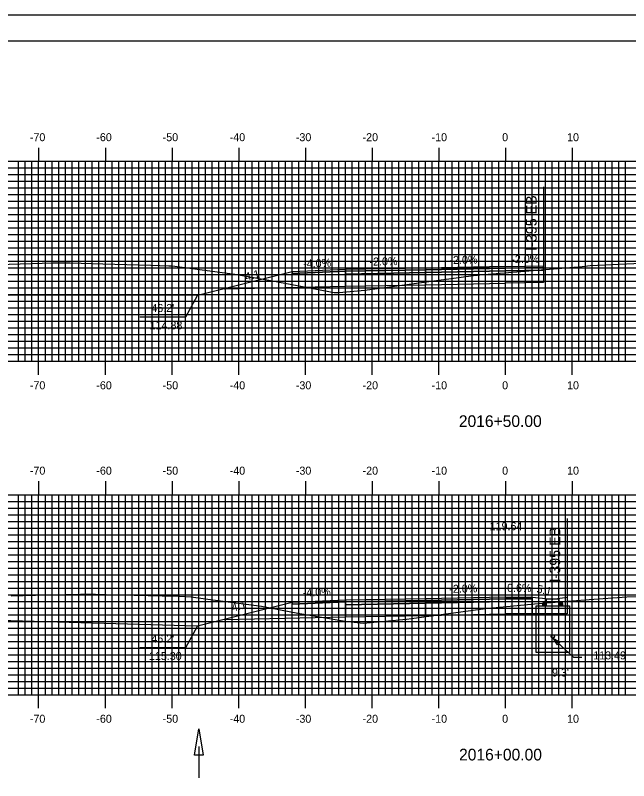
# Model space of a CAD drawing. Extents: x 854681 to 855024, y 366605 to 366825.
# Drawn here: x 854773.1 to 854865.1, y 366710.2 to 366824.9 of the extents above; entities that cross this region are included whole.
import ezdxf

# ---------------------------------------------------------------- set-up
doc = ezdxf.new("R2010")
doc.units = 0
for name, color, linetype in [('ANNOTATION', 7, 'Continuous'), ('BORDER', 7, 'Continuous'), ('D_Drainage_CB_TypeA1-B1', 7, 'Continuous'), ('D_Drainage_Culvert', 7, 'Continuous'), ('D_Drainage_Ditch_Line', 7, 'Continuous'), ('D_Roadway_Centerline', 7, 'Continuous'), ('D_Roadway_Centerline_Text', 7, 'Continuous'), ('D_Roadway_Edge_Shoulder', 7, 'Continuous'), ('D_Roadway_Edge_TW', 7, 'Continuous'), ('D_Roadway_Pavement', 7, 'Continuous'), ('D_Roadway_SlopeLines', 7, 'Continuous'), ('D_Roadway_SubGrade', 7, 'Continuous'), ('D_Text_Standard', 7, 'Continuous'), ('H_V ANNOTATION', 7, 'Continuous'), ('M_Roadway_Centerline', 7, 'Continuous'), ('MAJOR', 7, 'Continuous'), ('MINOR', 7, 'Continuous'), ('PLOT BOUNDARY', 7, 'Continuous'), ('S_Roadway_Centerline', 7, 'Continuous')]:
    doc.layers.add(name, color=color, linetype=linetype)

msp = doc.modelspace()

# ---------------------------------------------------------------- linework, layer by layer
at = {"layer": 'ANNOTATION'}
msp.add_line((854804.38, 366734.36), (854800.38, 366733.36), dxfattribs=at)
for points in [[(854804.38, 366783.93), (854800.38, 366782.93), (854734.03, 366782.96)], [(854791.72, 366779.72), (854798.65, 366779.72), (854800.38, 366782.93)], [(854804.38, 366734.36), (854800.38, 366733.36), (854742.57, 366734.98)], [(854791.72, 366730.15), (854798.65, 366730.15), (854800.38, 366733.36)]]:
    msp.add_lwpolyline(points, dxfattribs=at)
at = {"layer": 'BORDER'}
msp.add_lwpolyline([(854696.96, 366611.06), (855016.96, 366611.06), (855016.96, 366821.06), (854696.96, 366821.06)], close=True, dxfattribs=at)
at = {"layer": 'D_Drainage_CB_TypeA1-B1'}
msp.add_lwpolyline([(854855.17, 366736.78), (854854.64, 366736.78), (854854.64, 366737.41), (854852.67, 366737.41), (854852.67, 366736.78), (854852.15, 366736.78)], dxfattribs=at)
for points in [[(854856.15, 366729.41), (854851.17, 366729.41), (854851.17, 366736.4), (854856.15, 366736.4)], [(854852.67, 366736.72), (854852.67, 366736.47), (854852.17, 366736.47), (854852.17, 366736.72)], [(854855.14, 366736.72), (854855.14, 366736.47), (854854.64, 366736.47), (854854.64, 366736.72)]]:
    msp.add_lwpolyline(points, close=True, dxfattribs=at)
at = {"layer": 'D_Drainage_Culvert'}
msp.add_circle((854853.66, 366731.8), 0.25, dxfattribs=at)
at = {"layer": 'D_Drainage_Ditch_Line'}
msp.add_line((854800.59, 366715.32), (854800.59, 366710.62), dxfattribs=at)
msp.add_lwpolyline([(854801.25, 366714.01), (854799.94, 366714.01), (854800.59, 366717.94)], close=True, dxfattribs=at)
at = {"layer": 'D_Roadway_Centerline'}
for p, q in [((854855.81, 366737.67), (854855.81, 366735.18)), ((854855.81, 366735.18), (854850.56, 366735.18))]:
    msp.add_line(p, q, dxfattribs=at)
msp.add_lwpolyline([(854850.56, 366737.68), (854853.66, 366737.41), (854855.81, 366737.67)], dxfattribs=at)
at = {"layer": 'D_Roadway_Edge_Shoulder'}
for points in [[(854822.56, 366786.8), (854814.56, 366786.48), (854814.56, 366786.23), (854822.56, 366786.55)], [(854846.56, 366787.28), (854852.26, 366787.39), (854852.26, 366787.14), (854846.56, 366787.03)], [(854846.56, 366737.7), (854850.56, 366737.68), (854850.56, 366737.43), (854846.56, 366737.45)], [(854822.56, 366737.22), (854814.56, 366736.9), (854814.56, 366736.65), (854822.56, 366736.97)]]:
    msp.add_lwpolyline(points, close=True, dxfattribs=at)
at = {"layer": 'D_Roadway_Edge_TW'}
for points in [[(854834.56, 366787.04), (854822.56, 366786.8), (854822.56, 366786.55), (854834.56, 366786.79)], [(854846.56, 366787.28), (854834.56, 366787.04), (854834.56, 366786.79), (854846.56, 366787.03)], [(854834.56, 366737.46), (854822.56, 366737.22), (854822.56, 366736.97), (854834.56, 366737.21)], [(854846.56, 366737.7), (854834.56, 366737.46), (854834.56, 366737.21), (854846.56, 366737.45)]]:
    msp.add_lwpolyline(points, close=True, dxfattribs=at)
at = {"layer": 'D_Roadway_Pavement'}
for points in [[(854834.56, 366786.79), (854822.56, 366786.55), (854822.56, 366786.13), (854834.56, 366786.37)], [(854846.56, 366787.03), (854834.56, 366786.79), (854834.56, 366786.37), (854846.56, 366786.61)], [(854846.56, 366787.03), (854852.26, 366787.14), (854852.26, 366786.72), (854846.56, 366786.61)], [(854846.56, 366737.45), (854834.56, 366737.21), (854834.56, 366736.79), (854846.56, 366737.03)], [(854846.56, 366737.45), (854850.56, 366737.43), (854850.56, 366737.01), (854846.56, 366737.03)], [(854834.56, 366737.21), (854822.56, 366736.97), (854822.56, 366736.55), (854834.56, 366736.79)]]:
    msp.add_lwpolyline(points, close=True, dxfattribs=at)
for points in [[(854834.56, 366786.79), (854834.56, 366786.37)], [(854822.56, 366786.55), (854822.56, 366786.13)], [(854822.56, 366786.55), (854822.56, 366786.13)], [(854822.56, 366736.97), (854822.56, 366736.55)], [(854822.56, 366736.97), (854822.56, 366736.55)], [(854834.56, 366737.21), (854834.56, 366736.79)]]:
    msp.add_lwpolyline(points, dxfattribs=at)
at = {"layer": 'D_Roadway_SlopeLines'}
msp.add_line((854814.56, 366736.9), (854800.38, 366733.36), dxfattribs=at)
at = {"layer": 'D_Roadway_SubGrade'}
for p, q in [((854852.26, 366799.2), (854852.26, 366784.89)), ((854855.81, 366749.48), (854855.81, 366735.18))]:
    msp.add_line(p, q, dxfattribs=at)
for points in [[(854846.56, 366786.61), (854852.26, 366786.72), (854852.26, 366787.14), (854852.26, 366787.39), (854852.26, 366784.89), (854846.56, 366784.78)], [(854822.56, 366786.13), (854822.56, 366786.55), (854814.56, 366786.23), (854814.56, 366786.48), (854804.38, 366783.93), (854822.56, 366784.3)], [(854834.56, 366786.37), (854822.56, 366786.13), (854822.56, 366784.3), (854834.56, 366784.54)], [(854846.56, 366786.61), (854834.56, 366786.37), (854834.56, 366784.54), (854846.56, 366784.78)], [(854846.56, 366737.03), (854850.56, 366737.01), (854850.56, 366737.43), (854850.56, 366737.68), (854850.56, 366735.18), (854846.56, 366735.2)], [(854822.56, 366736.55), (854822.56, 366736.97), (854814.56, 366736.65), (854814.56, 366736.9), (854804.38, 366734.36), (854822.56, 366734.72)], [(854834.56, 366736.79), (854822.56, 366736.55), (854822.56, 366734.72), (854834.56, 366734.96)], [(854846.56, 366737.03), (854834.56, 366736.79), (854834.56, 366734.96), (854846.56, 366735.2)]]:
    msp.add_lwpolyline(points, close=True, dxfattribs=at)
at = {"layer": 'D_Text_Standard'}
msp.add_lwpolyline([(854853.66, 366731.55), (854854.31, 366730.54), (854854.71, 366730.96)], close=True, dxfattribs=at)
msp.add_lwpolyline([(854853.66, 366731.55), (854856.76, 366728.67), (854858, 366728.67)], dxfattribs=at)
at = {"layer": 'MAJOR'}
for p, q in [((854776.56, 366805.06), (854776.56, 366803.06)), ((854786.56, 366805.06), (854786.56, 366803.06)), ((854796.56, 366805.06), (854796.56, 366803.06)), ((854806.56, 366805.06), (854806.56, 366803.06)), ((854816.56, 366805.06), (854816.56, 366803.06)), ((854826.56, 366805.06), (854826.56, 366803.06)), ((854836.56, 366805.06), (854836.56, 366803.06)), ((854846.56, 366805.06), (854846.56, 366803.06)), ((854856.56, 366805.06), (854856.56, 366803.06)), ((854706.56, 366803.06), (854986.56, 366803.06)), ((854706.56, 366803.06), (854986.56, 366803.06)), ((854776.56, 366773.06), (854776.56, 366803.06)), ((854786.56, 366773.06), (854786.56, 366803.06)), ((854796.56, 366773.06), (854796.56, 366803.06)), ((854806.56, 366773.06), (854806.56, 366803.06)), ((854816.56, 366773.06), (854816.56, 366803.06)), ((854826.56, 366773.06), (854826.56, 366803.06)), ((854836.56, 366773.06), (854836.56, 366803.06)), ((854846.56, 366773.06), (854846.56, 366803.06)), ((854856.56, 366773.06), (854856.56, 366803.06)), ((854706.56, 366798.06), (854986.56, 366798.06)), ((854706.56, 366793.06), (854986.56, 366793.06)), ((854706.56, 366788.06), (854986.56, 366788.06)), ((854706.56, 366783.06), (854986.56, 366783.06)), ((854706.56, 366778.06), (854986.56, 366778.06)), ((854706.56, 366773.06), (854986.56, 366773.06)), ((854706.56, 366773.06), (854986.56, 366773.06)), ((854776.56, 366771.05), (854776.56, 366773.06)), ((854786.56, 366771.05), (854786.56, 366773.06)), ((854796.56, 366771.05), (854796.56, 366773.06)), ((854806.56, 366771.05), (854806.56, 366773.06)), ((854816.56, 366771.05), (854816.56, 366773.06)), ((854826.56, 366771.05), (854826.56, 366773.06)), ((854836.56, 366771.05), (854836.56, 366773.06)), ((854846.56, 366771.05), (854846.56, 366773.06)), ((854856.56, 366771.05), (854856.56, 366773.06)), ((854776.56, 366755.06), (854776.56, 366753.06)), ((854786.56, 366755.06), (854786.56, 366753.06)), ((854796.56, 366755.06), (854796.56, 366753.06)), ((854806.56, 366755.06), (854806.56, 366753.06)), ((854816.56, 366755.06), (854816.56, 366753.06)), ((854826.56, 366755.06), (854826.56, 366753.06)), ((854836.56, 366755.06), (854836.56, 366753.06)), ((854846.56, 366755.06), (854846.56, 366753.06)), ((854856.56, 366755.06), (854856.56, 366753.06)), ((854706.56, 366753.06), (854986.56, 366753.06)), ((854706.56, 366753.06), (854986.56, 366753.06)), ((854776.56, 366723.06), (854776.56, 366753.06)), ((854786.56, 366723.06), (854786.56, 366753.06)), ((854796.56, 366723.06), (854796.56, 366753.06)), ((854806.56, 366723.06), (854806.56, 366753.06)), ((854816.56, 366723.06), (854816.56, 366753.06)), ((854826.56, 366723.06), (854826.56, 366753.06)), ((854836.56, 366723.06), (854836.56, 366753.06)), ((854846.56, 366723.06), (854846.56, 366753.06)), ((854856.56, 366723.06), (854856.56, 366753.06)), ((854706.56, 366748.06), (854986.56, 366748.06)), ((854706.56, 366743.06), (854986.56, 366743.06)), ((854706.56, 366738.06), (854986.56, 366738.06)), ((854706.56, 366733.06), (854986.56, 366733.06)), ((854706.56, 366728.06), (854986.56, 366728.06)), ((854706.56, 366723.06), (854986.56, 366723.06)), ((854706.56, 366723.06), (854986.56, 366723.06)), ((854776.56, 366721.05), (854776.56, 366723.06)), ((854786.56, 366721.05), (854786.56, 366723.06)), ((854796.56, 366721.05), (854796.56, 366723.06)), ((854806.56, 366721.05), (854806.56, 366723.06)), ((854816.56, 366721.05), (854816.56, 366723.06)), ((854826.56, 366721.05), (854826.56, 366723.06)), ((854836.56, 366721.05), (854836.56, 366723.06)), ((854846.56, 366721.05), (854846.56, 366723.06)), ((854856.56, 366721.05), (854856.56, 366723.06))]:
    msp.add_line(p, q, dxfattribs=at)
at = {"layer": 'MINOR'}
for p, q in [((854773.56, 366773.06), (854773.56, 366803.06)), ((854774.56, 366773.06), (854774.56, 366803.06)), ((854775.56, 366773.06), (854775.56, 366803.06)), ((854777.56, 366773.06), (854777.56, 366803.06)), ((854778.56, 366773.06), (854778.56, 366803.06)), ((854779.56, 366773.06), (854779.56, 366803.06)), ((854780.56, 366773.06), (854780.56, 366803.06)), ((854781.56, 366773.06), (854781.56, 366803.06)), ((854782.56, 366773.06), (854782.56, 366803.06)), ((854783.56, 366773.06), (854783.56, 366803.06)), ((854784.56, 366773.06), (854784.56, 366803.06)), ((854785.56, 366773.06), (854785.56, 366803.06)), ((854787.56, 366773.06), (854787.56, 366803.06)), ((854788.56, 366773.06), (854788.56, 366803.06)), ((854789.56, 366773.06), (854789.56, 366803.06)), ((854790.56, 366773.06), (854790.56, 366803.06)), ((854791.56, 366773.06), (854791.56, 366803.06)), ((854792.56, 366773.06), (854792.56, 366803.06)), ((854793.56, 366773.06), (854793.56, 366803.06)), ((854794.56, 366773.06), (854794.56, 366803.06)), ((854795.56, 366773.06), (854795.56, 366803.06)), ((854797.56, 366773.06), (854797.56, 366803.06)), ((854798.56, 366773.06), (854798.56, 366803.06)), ((854799.56, 366773.06), (854799.56, 366803.06)), ((854800.56, 366773.06), (854800.56, 366803.06)), ((854801.56, 366773.06), (854801.56, 366803.06)), ((854802.56, 366773.06), (854802.56, 366803.06)), ((854803.56, 366773.06), (854803.56, 366803.06)), ((854804.56, 366773.06), (854804.56, 366803.06)), ((854805.56, 366773.06), (854805.56, 366803.06)), ((854807.56, 366773.06), (854807.56, 366803.06)), ((854808.56, 366773.06), (854808.56, 366803.06)), ((854809.56, 366773.06), (854809.56, 366803.06)), ((854810.56, 366773.06), (854810.56, 366803.06)), ((854811.56, 366773.06), (854811.56, 366803.06)), ((854812.56, 366773.06), (854812.56, 366803.06)), ((854813.56, 366773.06), (854813.56, 366803.06)), ((854814.56, 366773.06), (854814.56, 366803.06)), ((854815.56, 366773.06), (854815.56, 366803.06)), ((854817.56, 366773.06), (854817.56, 366803.06)), ((854818.56, 366773.06), (854818.56, 366803.06)), ((854819.56, 366773.06), (854819.56, 366803.06)), ((854820.56, 366773.06), (854820.56, 366803.06)), ((854821.56, 366773.06), (854821.56, 366803.06)), ((854822.56, 366773.06), (854822.56, 366803.06)), ((854823.56, 366773.06), (854823.56, 366803.06)), ((854824.56, 366773.06), (854824.56, 366803.06)), ((854825.56, 366773.06), (854825.56, 366803.06)), ((854827.56, 366773.06), (854827.56, 366803.06)), ((854828.56, 366773.06), (854828.56, 366803.06)), ((854829.56, 366773.06), (854829.56, 366803.06)), ((854830.56, 366773.06), (854830.56, 366803.06)), ((854831.56, 366773.06), (854831.56, 366803.06)), ((854832.56, 366773.06), (854832.56, 366803.06)), ((854833.56, 366773.06), (854833.56, 366803.06)), ((854834.56, 366773.06), (854834.56, 366803.06)), ((854835.56, 366773.06), (854835.56, 366803.06)), ((854837.56, 366773.06), (854837.56, 366803.06)), ((854838.56, 366773.06), (854838.56, 366803.06)), ((854839.56, 366773.06), (854839.56, 366803.06)), ((854840.56, 366773.06), (854840.56, 366803.06)), ((854841.56, 366773.06), (854841.56, 366803.06)), ((854842.56, 366773.06), (854842.56, 366803.06)), ((854843.56, 366773.06), (854843.56, 366803.06)), ((854844.56, 366773.06), (854844.56, 366803.06)), ((854845.56, 366773.06), (854845.56, 366803.06)), ((854847.56, 366773.06), (854847.56, 366803.06)), ((854848.56, 366773.06), (854848.56, 366803.06)), ((854849.56, 366773.06), (854849.56, 366803.06)), ((854850.56, 366773.06), (854850.56, 366803.06)), ((854851.56, 366773.06), (854851.56, 366803.06)), ((854852.56, 366773.06), (854852.56, 366803.06)), ((854853.56, 366773.06), (854853.56, 366803.06)), ((854854.56, 366773.06), (854854.56, 366803.06)), ((854855.56, 366773.06), (854855.56, 366803.06)), ((854857.56, 366773.06), (854857.56, 366803.06)), ((854858.56, 366773.06), (854858.56, 366803.06)), ((854859.56, 366773.06), (854859.56, 366803.06)), ((854860.56, 366773.06), (854860.56, 366803.06)), ((854861.56, 366773.06), (854861.56, 366803.06)), ((854862.56, 366773.06), (854862.56, 366803.06)), ((854863.56, 366773.06), (854863.56, 366803.06)), ((854864.56, 366773.06), (854864.56, 366803.06)), ((854706.56, 366802.06), (854986.56, 366802.06)), ((854706.56, 366801.06), (854986.56, 366801.06)), ((854706.56, 366800.06), (854986.56, 366800.06)), ((854706.56, 366799.06), (854986.56, 366799.06)), ((854706.56, 366797.06), (854986.56, 366797.06)), ((854706.56, 366796.06), (854986.56, 366796.06)), ((854706.56, 366795.06), (854986.56, 366795.06)), ((854706.56, 366794.06), (854986.56, 366794.06)), ((854706.56, 366792.06), (854986.56, 366792.06)), ((854706.56, 366791.06), (854986.56, 366791.06)), ((854706.56, 366790.06), (854986.56, 366790.06)), ((854706.56, 366789.06), (854986.56, 366789.06)), ((854706.56, 366787.06), (854986.56, 366787.06)), ((854706.56, 366786.06), (854986.56, 366786.06)), ((854706.56, 366785.06), (854986.56, 366785.06)), ((854706.56, 366784.06), (854986.56, 366784.06)), ((854706.56, 366782.06), (854986.56, 366782.06)), ((854706.56, 366781.06), (854986.56, 366781.06)), ((854706.56, 366780.06), (854986.56, 366780.06)), ((854706.56, 366779.06), (854986.56, 366779.06)), ((854706.56, 366777.06), (854986.56, 366777.06)), ((854706.56, 366776.06), (854986.56, 366776.06)), ((854706.56, 366775.06), (854986.56, 366775.06)), ((854706.56, 366774.06), (854986.56, 366774.06)), ((854773.56, 366723.06), (854773.56, 366753.06)), ((854774.56, 366723.06), (854774.56, 366753.06)), ((854775.56, 366723.06), (854775.56, 366753.06)), ((854777.56, 366723.06), (854777.56, 366753.06)), ((854778.56, 366723.06), (854778.56, 366753.06)), ((854779.56, 366723.06), (854779.56, 366753.06)), ((854780.56, 366723.06), (854780.56, 366753.06)), ((854781.56, 366723.06), (854781.56, 366753.06)), ((854782.56, 366723.06), (854782.56, 366753.06)), ((854783.56, 366723.06), (854783.56, 366753.06)), ((854784.56, 366723.06), (854784.56, 366753.06)), ((854785.56, 366723.06), (854785.56, 366753.06)), ((854787.56, 366723.06), (854787.56, 366753.06)), ((854788.56, 366723.06), (854788.56, 366753.06)), ((854789.56, 366723.06), (854789.56, 366753.06)), ((854790.56, 366723.06), (854790.56, 366753.06)), ((854791.56, 366723.06), (854791.56, 366753.06)), ((854792.56, 366723.06), (854792.56, 366753.06)), ((854793.56, 366723.06), (854793.56, 366753.06)), ((854794.56, 366723.06), (854794.56, 366753.06)), ((854795.56, 366723.06), (854795.56, 366753.06)), ((854797.56, 366723.06), (854797.56, 366753.06)), ((854798.56, 366723.06), (854798.56, 366753.06)), ((854799.56, 366723.06), (854799.56, 366753.06)), ((854800.56, 366723.06), (854800.56, 366753.06)), ((854801.56, 366723.06), (854801.56, 366753.06)), ((854802.56, 366723.06), (854802.56, 366753.06)), ((854803.56, 366723.06), (854803.56, 366753.06)), ((854804.56, 366723.06), (854804.56, 366753.06)), ((854805.56, 366723.06), (854805.56, 366753.06)), ((854807.56, 366723.06), (854807.56, 366753.06)), ((854808.56, 366723.06), (854808.56, 366753.06)), ((854809.56, 366723.06), (854809.56, 366753.06)), ((854810.56, 366723.06), (854810.56, 366753.06)), ((854811.56, 366723.06), (854811.56, 366753.06)), ((854812.56, 366723.06), (854812.56, 366753.06)), ((854813.56, 366723.06), (854813.56, 366753.06)), ((854814.56, 366723.06), (854814.56, 366753.06)), ((854815.56, 366723.06), (854815.56, 366753.06)), ((854817.56, 366723.06), (854817.56, 366753.06)), ((854818.56, 366723.06), (854818.56, 366753.06)), ((854819.56, 366723.06), (854819.56, 366753.06)), ((854820.56, 366723.06), (854820.56, 366753.06)), ((854821.56, 366723.06), (854821.56, 366753.06)), ((854822.56, 366723.06), (854822.56, 366753.06)), ((854823.56, 366723.06), (854823.56, 366753.06)), ((854824.56, 366723.06), (854824.56, 366753.06)), ((854825.56, 366723.06), (854825.56, 366753.06)), ((854827.56, 366723.06), (854827.56, 366753.06)), ((854828.56, 366723.06), (854828.56, 366753.06)), ((854829.56, 366723.06), (854829.56, 366753.06)), ((854830.56, 366723.06), (854830.56, 366753.06)), ((854831.56, 366723.06), (854831.56, 366753.06)), ((854832.56, 366723.06), (854832.56, 366753.06)), ((854833.56, 366723.06), (854833.56, 366753.06)), ((854834.56, 366723.06), (854834.56, 366753.06)), ((854835.56, 366723.06), (854835.56, 366753.06)), ((854837.56, 366723.06), (854837.56, 366753.06)), ((854838.56, 366723.06), (854838.56, 366753.06)), ((854839.56, 366723.06), (854839.56, 366753.06)), ((854840.56, 366723.06), (854840.56, 366753.06)), ((854841.56, 366723.06), (854841.56, 366753.06)), ((854842.56, 366723.06), (854842.56, 366753.06)), ((854843.56, 366723.06), (854843.56, 366753.06)), ((854844.56, 366723.06), (854844.56, 366753.06)), ((854845.56, 366723.06), (854845.56, 366753.06)), ((854847.56, 366723.06), (854847.56, 366753.06)), ((854848.56, 366723.06), (854848.56, 366753.06)), ((854849.56, 366723.06), (854849.56, 366753.06)), ((854850.56, 366723.06), (854850.56, 366753.06)), ((854851.56, 366723.06), (854851.56, 366753.06)), ((854852.56, 366723.06), (854852.56, 366753.06)), ((854853.56, 366723.06), (854853.56, 366753.06)), ((854854.56, 366723.06), (854854.56, 366753.06)), ((854855.56, 366723.06), (854855.56, 366753.06)), ((854857.56, 366723.06), (854857.56, 366753.06)), ((854858.56, 366723.06), (854858.56, 366753.06)), ((854859.56, 366723.06), (854859.56, 366753.06)), ((854860.56, 366723.06), (854860.56, 366753.06)), ((854861.56, 366723.06), (854861.56, 366753.06)), ((854862.56, 366723.06), (854862.56, 366753.06)), ((854863.56, 366723.06), (854863.56, 366753.06)), ((854864.56, 366723.06), (854864.56, 366753.06)), ((854706.56, 366752.06), (854986.56, 366752.06)), ((854706.56, 366751.06), (854986.56, 366751.06)), ((854706.56, 366750.06), (854986.56, 366750.06)), ((854706.56, 366749.06), (854986.56, 366749.06)), ((854706.56, 366747.06), (854986.56, 366747.06)), ((854706.56, 366746.06), (854986.56, 366746.06)), ((854706.56, 366745.06), (854986.56, 366745.06)), ((854706.56, 366744.06), (854986.56, 366744.06)), ((854706.56, 366742.06), (854986.56, 366742.06)), ((854706.56, 366741.06), (854986.56, 366741.06)), ((854706.56, 366740.06), (854986.56, 366740.06)), ((854706.56, 366739.06), (854986.56, 366739.06)), ((854706.56, 366737.06), (854986.56, 366737.06)), ((854706.56, 366736.06), (854986.56, 366736.06)), ((854706.56, 366735.06), (854986.56, 366735.06)), ((854706.56, 366734.06), (854986.56, 366734.06)), ((854706.56, 366732.06), (854986.56, 366732.06)), ((854706.56, 366731.06), (854986.56, 366731.06)), ((854706.56, 366730.06), (854986.56, 366730.06)), ((854706.56, 366729.06), (854986.56, 366729.06)), ((854706.56, 366727.06), (854986.56, 366727.06)), ((854706.56, 366726.06), (854986.56, 366726.06)), ((854706.56, 366725.06), (854986.56, 366725.06)), ((854706.56, 366724.06), (854986.56, 366724.06))]:
    msp.add_line(p, q, dxfattribs=at)
at = {"layer": 'PLOT BOUNDARY'}
msp.add_lwpolyline([(854680.77, 366604.94), (855020.77, 366604.94), (855020.77, 366824.94), (854680.77, 366824.94)], close=True, dxfattribs=at)
at = {"layer": 'S_Roadway_Centerline'}
for points in [[(854767.13, 366787.45), (854778.72, 366787.8), (854780.25, 366787.84), (854780.28, 366787.84), (854780.5, 366787.84), (854781.26, 366787.82), (854786.19, 366787.67), (854793.36, 366787.46), (854796.09, 366787.39), (854796.42, 366787.38), (854796.58, 366787.35), (854805.98, 366786.1), (854811.62, 366785.13), (854820.9, 366783.37), (854821.61, 366783.35), (854825.49, 366783.72), (854842.12, 366785.95), (854842.37, 366785.98), (854842.5, 366786), (854842.71, 366786.01), (854858.09, 366787.26), (854859.27, 366787.44), (854871.29, 366787.96)], [(854772.42, 366737.9), (854776.1, 366737.98), (854782.85, 366738.13), (854783.51, 366738.18), (854786.68, 366738.11), (854795.1, 366737.91), (854795.29, 366737.9), (854796.8, 366737.87), (854799.41, 366737.76), (854801.91, 366737.41), (854809.96, 366736.35), (854815.41, 366735.31), (854822.51, 366734.08), (854825.23, 366733.78), (854831.73, 366734.4), (854832.49, 366734.5), (854843.6, 366736), (854851.46, 366736.73), (854859.12, 366737.35), (854864.78, 366737.76), (854868.15, 366737.84)]]:
    msp.add_lwpolyline(points, dxfattribs=at)

# ---------------------------------------------------------------- texts
at = {"layer": 'ANNOTATION'}
for s, height, rotation, p in [('I-395 EB', 1.6, 90, (854851.25, 366789.62)), ('-2.0%', 1.2, 1.1458, (854847.46, 366787.76)), ('-4.0%', 1.2, 2.2905, (854816.25, 366787.08)), ('-2.0%', 1.2, 1.1458, (854826.19, 366787.4)), ('-2.0%', 1.2, 1.1458, (854838.19, 366787.64)), ('4:1', 1.2, 14.0341, (854807.66, 366785.11)), ("46.2' ", 1.2, 360, (854793.46, 366780.45)), ('114.88', 1.2, 360, (854793.2, 366777.85)), ('I-395 EB', 1.6, 90, (854854.79, 366739.9)), ('-2.0%', 1.2, 1.1458, (854838.16, 366738.33)), ('-0.6%', 1.2, 359.6706, (854846.28, 366738.5)), ('-4.0%', 1.2, 2.2905, (854816.19, 366737.77)), ('5:1', 1.2, 348.1827, (854851.17, 366738.39)), ('4:1', 1.2, 14.0341, (854805.64, 366735.53)), ("46.2' ", 1.2, 360, (854793.46, 366730.87)), ('115.30', 1.2, 360, (854793.1, 366728.27))]:
    msp.add_text(s, height=height, rotation=rotation, dxfattribs=at).set_placement(p)
at = {"layer": 'D_Roadway_Centerline_Text'}
msp.add_text('119.64', height=1.2, dxfattribs=at).set_placement((854844.2, 366747.73))
at = {"layer": 'D_Text_Standard'}
for s, p in [('113.49', (854859.73, 366728.36)), ("9.3'", (854853.55, 366725.8))]:
    msp.add_text(s, height=1.2, dxfattribs=at).set_placement(p)
at = {"layer": 'H_V ANNOTATION'}
for s, height, p in [('-70', 1.2, (854775.24, 366806.06)), ('-60', 1.2, (854785.21, 366806.06)), ('-50', 1.2, (854795.16, 366806.06)), ('-40', 1.2, (854805.21, 366806.06)), ('-30', 1.2, (854815.13, 366806.06)), ('-20', 1.2, (854825.14, 366806.06)), ('-10', 1.2, (854835.49, 366806.06)), ('0', 1.2, (854846.07, 366806.06)), ('10', 1.2, (854855.81, 366806.06)), ('-70', 1.2, (854775.24, 366768.86)), ('-60', 1.2, (854785.21, 366768.86)), ('-50', 1.2, (854795.16, 366768.86)), ('-40', 1.2, (854805.21, 366768.86)), ('-30', 1.2, (854815.13, 366768.86)), ('-20', 1.2, (854825.14, 366768.86)), ('-10', 1.2, (854835.49, 366768.86)), ('0', 1.2, (854846.07, 366768.86)), ('10', 1.2, (854855.81, 366768.86)), ('2016+50.00', 1.75, (854839.58, 366763.21)), ('-70', 1.2, (854775.24, 366756.06)), ('-60', 1.2, (854785.21, 366756.06)), ('-50', 1.2, (854795.16, 366756.06)), ('-40', 1.2, (854805.21, 366756.06)), ('-30', 1.2, (854815.13, 366756.06)), ('-20', 1.2, (854825.14, 366756.06)), ('-10', 1.2, (854835.49, 366756.06)), ('0', 1.2, (854846.07, 366756.06)), ('10', 1.2, (854855.81, 366756.06)), ('-70', 1.2, (854775.24, 366718.86)), ('-60', 1.2, (854785.21, 366718.86)), ('-50', 1.2, (854795.16, 366718.86)), ('-40', 1.2, (854805.21, 366718.86)), ('-30', 1.2, (854815.13, 366718.86)), ('-20', 1.2, (854825.14, 366718.86)), ('-10', 1.2, (854835.49, 366718.86)), ('0', 1.2, (854846.07, 366718.86)), ('10', 1.2, (854855.81, 366718.86)), ('2016+00.00', 1.75, (854839.61, 366713.21))]:
    msp.add_text(s, height=height, dxfattribs=at).set_placement(p)
at = {"layer": 'M_Roadway_Centerline'}
for s, p in [('C', (854780.28, 366787.84)), ('L', (854780.28, 366787.83)), ('C', (854783.51, 366738.18)), ('L', (854783.51, 366738.17))]:
    msp.add_text(s, height=0.0146, dxfattribs=at).set_placement(p)

doc.saveas('drawing.dxf')
